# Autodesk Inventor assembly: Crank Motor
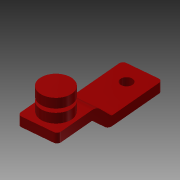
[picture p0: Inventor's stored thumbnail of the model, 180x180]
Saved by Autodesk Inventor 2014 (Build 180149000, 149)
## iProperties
Created: 2006-03
Part Number: Crank Motor
Document SubType Name: Assembly
Designer: Autodesk, Inc.
Mass: 66.6537 g
Surface Area: 48.811 cm^2
Volume: 8.60048 cm^3
Density: 7.75 g/cm^3
Author: Autodesk, Inc.
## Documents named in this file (3)
- C:\Users\iTools\Desktop\tutorial files\Dynamic Simulation 4\Components\Crank Motor.iam
- C:\Users\iTools\Desktop\tutorial files\Dynamic Simulation 4\Components\Crank_motor.ipt
- C:\Users\iTools\Desktop\tutorial files\Dynamic Simulation 4\Components\Pawn.ipt
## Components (2 placed, 2 different names)
1. Crank_motor:1 — Mate:1, Mate:2
2. Pawn:1 — Mate:1, Mate:2
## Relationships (2: Mate 2)
- Mate:1: Crank_motor:1 ↔ Pawn:1
- Mate:2: Crank_motor:1 ↔ Pawn:1
